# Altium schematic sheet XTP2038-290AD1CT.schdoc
size 127 x 101 mm
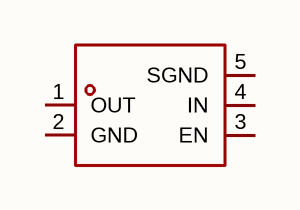
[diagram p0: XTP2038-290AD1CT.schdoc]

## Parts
U?  xtp2038-290ad1ct  [UDFN-4_L1.0-W1.0-P0.65-BL-EP]  (value not drawn)

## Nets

Not connected (* = marked no-connect by the designer): U? 1(OUT) 2(GND) 3(EN) 4(IN) 5(SGND)

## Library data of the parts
U? = xtp2038-290ad1ct: 输出极性:正极;工作电压:5.5V;输出电压:2.9V;输出电流:500mA;电源纹波抑制比(PSRR):-;输出类型:固定;; Manufacturer: XTX(芯天下); AddInBom: yes; ModelId: c1a489df884542e2aa77aee3d93f92e3; ModelName: UDFN-4_L1.0-W1.0-H0.6-P0.65-BL-EP; ModelTransform: 40.1574,40.1574,0,0,0,0,0,0,0; Output Configuration: 正极; Voltage - Supply: 5.5V; Output Voltage: 2.9V; Output Current: 500mA; Voltage Dropout: 180mV@(300mA); standby current: 15uA; Output Type: 固定; Number of Outputs: 1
